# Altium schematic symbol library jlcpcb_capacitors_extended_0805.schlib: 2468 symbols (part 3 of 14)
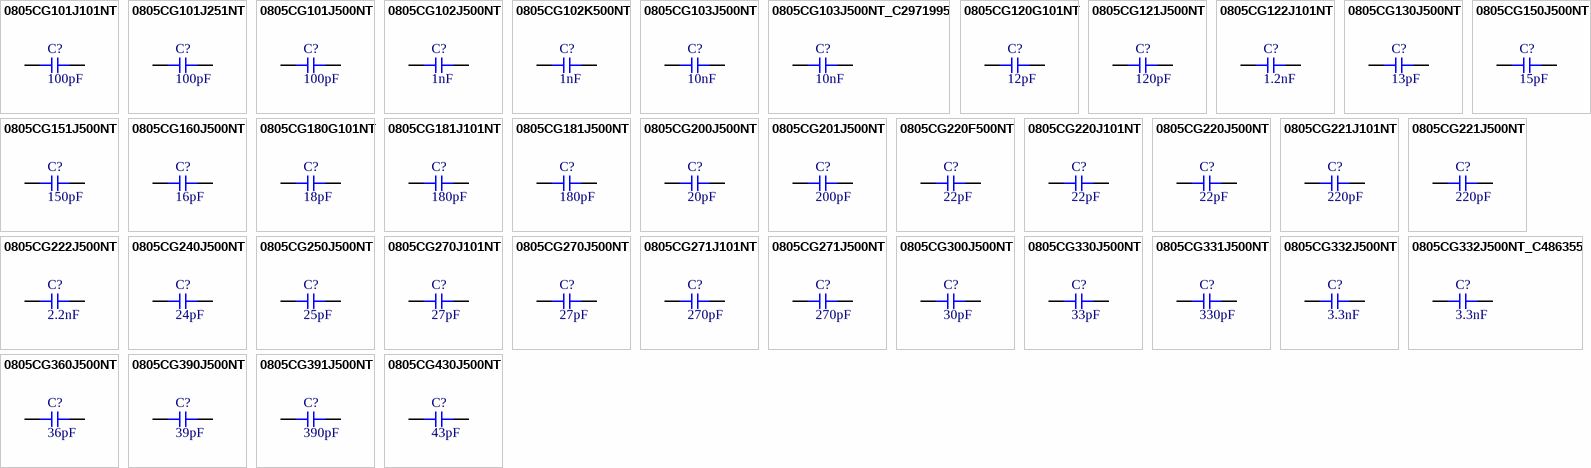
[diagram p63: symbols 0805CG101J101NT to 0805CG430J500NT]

## 0805CG390J500NT
designator C?  Capacitance: 39pF  (hidden comment: *)
Capacitor, Ceramic (MLCC), 39pF, ±5%, 50V, C0G, ±5%, SMD 0805; Manufacturer: FH(Guangdong Fenghua Advanced Tech); Manufacturer Part Number: 0805CG390J500NT
footprint CAP-0805 (0805 (2012M) Capacitor)
pins: 1, 2

## 0805CG391J500NT
designator C?  Capacitance: 390pF  (hidden comment: *)
Capacitor, Ceramic (MLCC), 390pF, ±5%, 50V, C0G, ±5%, SMD 0805; Manufacturer: FH(Guangdong Fenghua Advanced Tech); Manufacturer Part Number: 0805CG391J500NT
footprint CAP-0805 (0805 (2012M) Capacitor)
pins: 1, 2

## 0805CG430J500NT
designator C?  Capacitance: 43pF  (hidden comment: *)
Capacitor, Ceramic (MLCC), 43pF, ±5%, 50V, C0G, ±5%, SMD 0805; Manufacturer: FH(Guangdong Fenghua Advanced Tech); Manufacturer Part Number: 0805CG430J500NT
footprint CAP-0805 (0805 (2012M) Capacitor)
pins: 1, 2

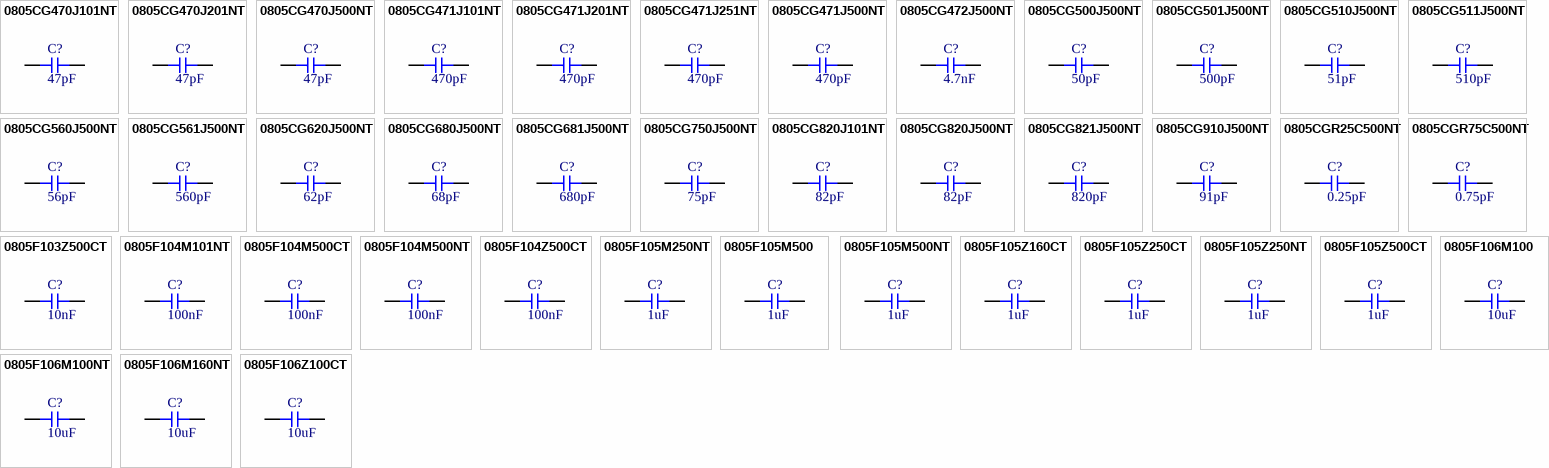
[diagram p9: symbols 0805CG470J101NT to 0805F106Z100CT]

## 0805CG470J101NT
designator C?  Capacitance: 47pF  (hidden comment: *)
Capacitor, Ceramic (MLCC), 47pF, ±5%, 100V, C0G, ±5%, SMD 0805; Manufacturer: FH(Guangdong Fenghua Advanced Tech); Manufacturer Part Number: 0805CG470J101NT
footprint CAP-0805 (0805 (2012M) Capacitor)
pins: 1, 2

## 0805CG470J201NT
designator C?  Capacitance: 47pF  (hidden comment: *)
Capacitor, Ceramic (MLCC), 47pF, ±5%, 200V, C0G, ±5%, SMD 0805; Manufacturer: FH(Guangdong Fenghua Advanced Tech); Manufacturer Part Number: 0805CG470J201NT
footprint CAP-0805 (0805 (2012M) Capacitor)
pins: 1, 2

## 0805CG470J500NT
designator C?  Capacitance: 47pF  (hidden comment: *)
Capacitor, Ceramic (MLCC), 47pF, ±5%, 50V, C0G, ±5%, SMD 0805; Manufacturer: FH(Guangdong Fenghua Advanced Tech); Manufacturer Part Number: 0805CG470J500NT
footprint CAP-0805 (0805 (2012M) Capacitor)
pins: 1, 2

## 0805CG471J101NT
designator C?  Capacitance: 470pF  (hidden comment: *)
Capacitor, Ceramic (MLCC), 470pF, ±5%, 100V, ±5%, SMD 0805; Manufacturer: FH(Guangdong Fenghua Advanced Tech); Manufacturer Part Number: 0805CG471J101NT
footprint CAP-0805 (0805 (2012M) Capacitor)
pins: 1, 2

## 0805CG471J201NT
designator C?  Capacitance: 470pF  (hidden comment: *)
Capacitor, Ceramic (MLCC), 470pF, ±5%, 200V, ±5%, SMD 0805; Manufacturer: FH(Guangdong Fenghua Advanced Tech); Manufacturer Part Number: 0805CG471J201NT
footprint CAP-0805 (0805 (2012M) Capacitor)
pins: 1, 2

## 0805CG471J251NT
designator C?  Capacitance: 470pF  (hidden comment: *)
Capacitor, Ceramic (MLCC), 470pF, ±5%, 250V, C0G, ±5%, SMD 0805; Manufacturer: FH(Guangdong Fenghua Advanced Tech); Manufacturer Part Number: 0805CG471J251NT
footprint CAP-0805 (0805 (2012M) Capacitor)
pins: 1, 2

## 0805CG471J500NT
designator C?  Capacitance: 470pF  (hidden comment: *)
Capacitor, Ceramic (MLCC), 470pF, ±5%, 50V, C0G, ±5%, SMD 0805; Manufacturer: FH(Guangdong Fenghua Advanced Tech); Manufacturer Part Number: 0805CG471J500NT
footprint CAP-0805 (0805 (2012M) Capacitor)
pins: 1, 2

## 0805CG472J500NT
designator C?  Capacitance: 4.7nF  (hidden comment: *)
Capacitor, Ceramic (MLCC), 4.7nF, ±5%, 50V, C0G, ±5%, SMD 0805; Manufacturer: FH(Guangdong Fenghua Advanced Tech); Manufacturer Part Number: 0805CG472J500NT
footprint CAP-0805 (0805 (2012M) Capacitor)
pins: 1, 2

## 0805CG500J500NT
designator C?  Capacitance: 50pF  (hidden comment: *)
Capacitor, Ceramic (MLCC), 50pF, ±5%, 50V, C0G, ±5%, SMD 0805; Manufacturer: FH(Guangdong Fenghua Advanced Tech); Manufacturer Part Number: 0805CG500J500NT
footprint CAP-0805 (0805 (2012M) Capacitor)
pins: 1, 2

## 0805CG501J500NT
designator C?  Capacitance: 500pF  (hidden comment: *)
Capacitor, Ceramic (MLCC), 500pF, ±5%, 50V, C0G, ±5%, SMD 0805; Manufacturer: FH(Guangdong Fenghua Advanced Tech); Manufacturer Part Number: 0805CG501J500NT
footprint CAP-0805 (0805 (2012M) Capacitor)
pins: 1, 2

## 0805CG510J500NT
designator C?  Capacitance: 51pF  (hidden comment: *)
Capacitor, Ceramic (MLCC), 51pF, ±5%, 50V, C0G, ±5%, SMD 0805; Manufacturer: FH(Guangdong Fenghua Advanced Tech); Manufacturer Part Number: 0805CG510J500NT
footprint CAP-0805 (0805 (2012M) Capacitor)
pins: 1, 2

## 0805CG511J500NT
designator C?  Capacitance: 510pF  (hidden comment: *)
Capacitor, Ceramic (MLCC), 510pF, ±5%, 50V, C0G, ±5%, SMD 0805; Manufacturer: FH(Guangdong Fenghua Advanced Tech); Manufacturer Part Number: 0805CG511J500NT
footprint CAP-0805 (0805 (2012M) Capacitor)
pins: 1, 2

## 0805CG560J500NT
designator C?  Capacitance: 56pF  (hidden comment: *)
Capacitor, Ceramic (MLCC), 56pF, ±5%, 50V, C0G, ±5%, SMD 0805; Manufacturer: FH(Guangdong Fenghua Advanced Tech); Manufacturer Part Number: 0805CG560J500NT
footprint CAP-0805 (0805 (2012M) Capacitor)
pins: 1, 2

## 0805CG561J500NT
designator C?  Capacitance: 560pF  (hidden comment: *)
Capacitor, Ceramic (MLCC), 560pF, ±5%, 50V, C0G, ±5%, SMD 0805; Manufacturer: FH(Guangdong Fenghua Advanced Tech); Manufacturer Part Number: 0805CG561J500NT
footprint CAP-0805 (0805 (2012M) Capacitor)
pins: 1, 2

## 0805CG620J500NT
designator C?  Capacitance: 62pF  (hidden comment: *)
Capacitor, Ceramic (MLCC), 62pF, ±5%, 50V, C0G, ±5%, SMD 0805; Manufacturer: FH(Guangdong Fenghua Advanced Tech); Manufacturer Part Number: 0805CG620J500NT
footprint CAP-0805 (0805 (2012M) Capacitor)
pins: 1, 2

## 0805CG680J500NT
designator C?  Capacitance: 68pF  (hidden comment: *)
Capacitor, Ceramic (MLCC), 68pF, ±5%, 50V, C0G, ±5%, SMD 0805; Manufacturer: FH(Guangdong Fenghua Advanced Tech); Manufacturer Part Number: 0805CG680J500NT
footprint CAP-0805 (0805 (2012M) Capacitor)
pins: 1, 2

## 0805CG681J500NT
designator C?  Capacitance: 680pF  (hidden comment: *)
Capacitor, Ceramic (MLCC), 680pF, ±5%, 50V, C0G, ±5%, SMD 0805; Manufacturer: FH(Guangdong Fenghua Advanced Tech); Manufacturer Part Number: 0805CG681J500NT
footprint CAP-0805 (0805 (2012M) Capacitor)
pins: 1, 2

## 0805CG750J500NT
designator C?  Capacitance: 75pF  (hidden comment: *)
Capacitor, Ceramic (MLCC), 75pF, ±5%, 50V, C0G, ±5%, SMD 0805; Manufacturer: FH(Guangdong Fenghua Advanced Tech); Manufacturer Part Number: 0805CG750J500NT
footprint CAP-0805 (0805 (2012M) Capacitor)
pins: 1, 2

## 0805CG820J101NT
designator C?  Capacitance: 82pF  (hidden comment: *)
Capacitor, Ceramic (MLCC), 82pF, ±5%, 100V, ±5%, SMD 0805; Manufacturer: FH(Guangdong Fenghua Advanced Tech); Manufacturer Part Number: 0805CG820J101NT
footprint CAP-0805 (0805 (2012M) Capacitor)
pins: 1, 2

## 0805CG820J500NT
designator C?  Capacitance: 82pF  (hidden comment: *)
Capacitor, Ceramic (MLCC), 82pF, ±5%, 50V, C0G, ±5%, SMD 0805; Manufacturer: FH(Guangdong Fenghua Advanced Tech); Manufacturer Part Number: 0805CG820J500NT
footprint CAP-0805 (0805 (2012M) Capacitor)
pins: 1, 2

## 0805CG821J500NT
designator C?  Capacitance: 820pF  (hidden comment: *)
Capacitor, Ceramic (MLCC), 820pF, ±5%, 50V, C0G, ±5%, SMD 0805; Manufacturer: FH(Guangdong Fenghua Advanced Tech); Manufacturer Part Number: 0805CG821J500NT
footprint CAP-0805 (0805 (2012M) Capacitor)
pins: 1, 2

## 0805CG910J500NT
designator C?  Capacitance: 91pF  (hidden comment: *)
Capacitor, Ceramic (MLCC), 91pF, ±5%, 50V, C0G, ±5%, SMD 0805; Manufacturer: FH(Guangdong Fenghua Advanced Tech); Manufacturer Part Number: 0805CG910J500NT
footprint CAP-0805 (0805 (2012M) Capacitor)
pins: 1, 2

## 0805CGR25C500NT
designator C?  Capacitance: 0.25pF  (hidden comment: *)
Capacitor, Ceramic (MLCC), 0.25pF, ±0.25pF, 50V, C0G, ±0.25pF, SMD 0805; Manufacturer: FH(Guangdong Fenghua Advanced Tech); Manufacturer Part Number: 0805CGR25C500NT
footprint CAP-0805 (0805 (2012M) Capacitor)
pins: 1, 2

## 0805CGR75C500NT
designator C?  Capacitance: 0.75pF  (hidden comment: *)
Capacitor, Ceramic (MLCC), 0.75pF, ±0.25pF, 50V, C0G, ±0.25pF, SMD 0805; Manufacturer: FH(Guangdong Fenghua Advanced Tech); Manufacturer Part Number: 0805CGR75C500NT
footprint CAP-0805 (0805 (2012M) Capacitor)
pins: 1, 2

## 0805F103Z500CT
designator C?  Capacitance: 10nF  (hidden comment: *)
Capacitor, Ceramic (MLCC), 10nF, 50V, Y5V, SMD 0805; Manufacturer: Walsin Tech Corp; Manufacturer Part Number: 0805F103Z500CT; Temperature Rating: -20%~+80%
footprint CAP-0805 (0805 (2012M) Capacitor)
pins: 1, 2

## 0805F104M101NT
designator C?  Capacitance: 100nF  (hidden comment: *)
Capacitor, Ceramic (MLCC), 100nF, ±20%, 100V, Y5V, ±20%, SMD 0805; Manufacturer: FH(Guangdong Fenghua Advanced Tech); Manufacturer Part Number: 0805F104M101NT
footprint CAP-0805 (0805 (2012M) Capacitor)
pins: 1, 2

## 0805F104M500CT
designator C?  Capacitance: 100nF  (hidden comment: *)
Capacitor, Ceramic (MLCC), 100nF, ±20%, 50V, Y5V, ±20%, SMD 0805; Manufacturer: Walsin Tech Corp; Manufacturer Part Number: 0805F104M500CT
footprint CAP-0805 (0805 (2012M) Capacitor)
pins: 1, 2

## 0805F104M500NT
designator C?  Capacitance: 100nF  (hidden comment: *)
Capacitor, Ceramic (MLCC), 100nF, ±20%, 50V, Y5V, ±20%, SMD 0805; Manufacturer: FH(Guangdong Fenghua Advanced Tech); Manufacturer Part Number: 0805F104M500NT
footprint CAP-0805 (0805 (2012M) Capacitor)
pins: 1, 2

## 0805F104Z500CT
designator C?  Capacitance: 100nF  (hidden comment: *)
Capacitor, Ceramic (MLCC), 100nF, 50V, Y5V, SMD 0805; Manufacturer: Walsin Tech Corp; Manufacturer Part Number: 0805F104Z500CT; Temperature Rating: -20%~+80%
footprint CAP-0805 (0805 (2012M) Capacitor)
pins: 1, 2

## 0805F105M250NT
designator C?  Capacitance: 1uF  (hidden comment: *)
Capacitor, Ceramic (MLCC), 1uF, ±20%, 25V, Y5V, ±20%, SMD 0805; Manufacturer: FH(Guangdong Fenghua Advanced Tech); Manufacturer Part Number: 0805F105M250NT
footprint CAP-0805 (0805 (2012M) Capacitor)
pins: 1, 2

## 0805F105M500
designator C?  Capacitance: 1uF  (hidden comment: *)
Capacitor, Ceramic (MLCC), 1uF, ±20%, 50V, Y5V, ±20%, SMD 0805; Manufacturer: Walsin Tech Corp; Manufacturer Part Number: 0805F105M500
footprint CAP-0805 (0805 (2012M) Capacitor)
pins: 1, 2

## 0805F105M500NT
designator C?  Capacitance: 1uF  (hidden comment: *)
Capacitor, Ceramic (MLCC), 1uF, ±20%, 50V, Y5V, ±20%, SMD 0805; Manufacturer: FH(Guangdong Fenghua Advanced Tech); Manufacturer Part Number: 0805F105M500NT
footprint CAP-0805 (0805 (2012M) Capacitor)
pins: 1, 2

## 0805F105Z160CT
designator C?  Capacitance: 1uF  (hidden comment: *)
Capacitor, Ceramic (MLCC), 1uF, 16V, Y5V, SMD 0805; Manufacturer: Walsin Tech Corp; Manufacturer Part Number: 0805F105Z160CT; Temperature Rating: -20%~+80%
footprint CAP-0805 (0805 (2012M) Capacitor)
pins: 1, 2

## 0805F105Z250CT
designator C?  Capacitance: 1uF  (hidden comment: *)
Capacitor, Ceramic (MLCC), 1uF, 25V, Y5V, SMD 0805; Manufacturer: Walsin Tech Corp; Manufacturer Part Number: 0805F105Z250CT; Temperature Rating: -20%~+80%
footprint CAP-0805 (0805 (2012M) Capacitor)
pins: 1, 2

## 0805F105Z250NT
designator C?  Capacitance: 1uF  (hidden comment: *)
Capacitor, Ceramic (MLCC), 1uF, 25V, Y5V, SMD 0805; Manufacturer: FH(Guangdong Fenghua Advanced Tech); Manufacturer Part Number: 0805F105Z250NT; Temperature Rating: -20%~+80%
footprint CAP-0805 (0805 (2012M) Capacitor)
pins: 1, 2

## 0805F105Z500CT
designator C?  Capacitance: 1uF  (hidden comment: *)
Capacitor, Ceramic (MLCC), 1uF, 50V, Y5V, SMD 0805; Manufacturer: Walsin Tech Corp; Manufacturer Part Number: 0805F105Z500CT; Temperature Rating: -20%~+80%
footprint CAP-0805 (0805 (2012M) Capacitor)
pins: 1, 2

## 0805F106M100
designator C?  Capacitance: 10uF  (hidden comment: *)
Capacitor, Ceramic (MLCC), 10uF, ±20%, 10V, Y5V, ±20%, SMD 0805; Manufacturer: Walsin Tech Corp; Manufacturer Part Number: 0805F106M100
footprint CAP-0805 (0805 (2012M) Capacitor)
pins: 1, 2

## 0805F106M100NT
designator C?  Capacitance: 10uF  (hidden comment: *)
Capacitor, Ceramic (MLCC), 10uF, ±20%, 10V, Y5V, ±20%, SMD 0805; Manufacturer: FH(Guangdong Fenghua Advanced Tech); Manufacturer Part Number: 0805F106M100NT
footprint CAP-0805 (0805 (2012M) Capacitor)
pins: 1, 2

## 0805F106M160NT
designator C?  Capacitance: 10uF  (hidden comment: *)
Capacitor, Ceramic (MLCC), 10uF, ±20%, 16V, Y5V, ±20%, SMD 0805; Manufacturer: FH(Guangdong Fenghua Advanced Tech); Manufacturer Part Number: 0805F106M160NT
footprint CAP-0805 (0805 (2012M) Capacitor)
pins: 1, 2

## 0805F106Z100CT
designator C?  Capacitance: 10uF  (hidden comment: *)
Capacitor, Ceramic (MLCC), 10uF, 10V, Y5V, SMD 0805; Manufacturer: Walsin Tech Corp; Manufacturer Part Number: 0805F106Z100CT; Temperature Rating: -20%~+80%
footprint CAP-0805 (0805 (2012M) Capacitor)
pins: 1, 2

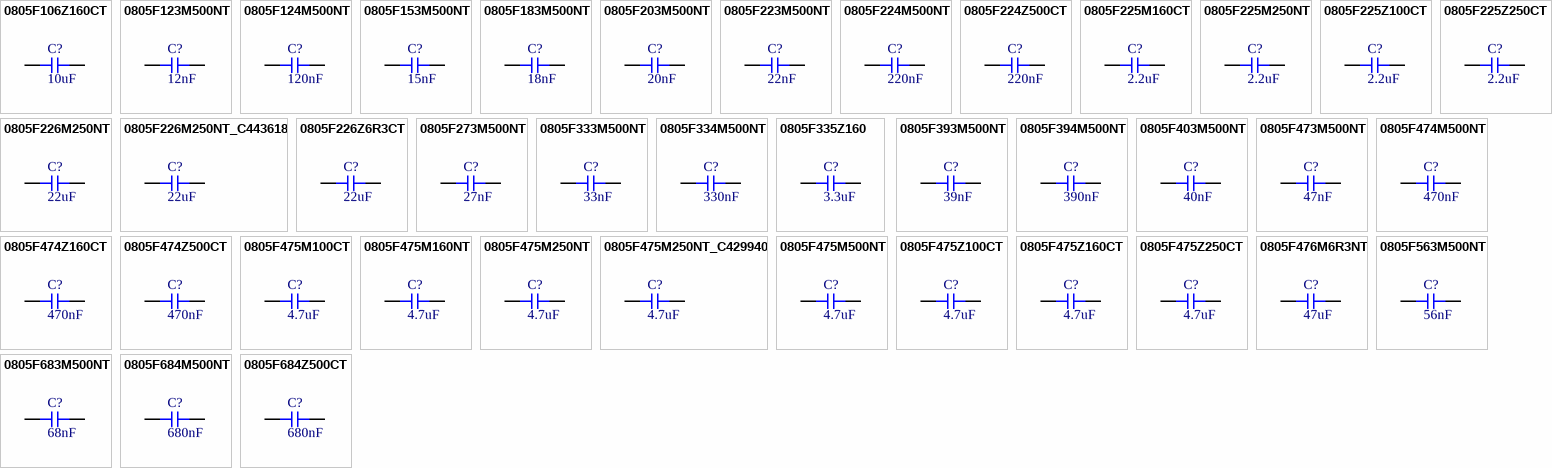
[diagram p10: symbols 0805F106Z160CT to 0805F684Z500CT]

## 0805F106Z160CT
designator C?  Capacitance: 10uF  (hidden comment: *)
Capacitor, Ceramic (MLCC), 10uF, 16V, Y5V, SMD 0805; Manufacturer: Walsin Tech Corp; Manufacturer Part Number: 0805F106Z160CT; Temperature Rating: -20%~+80%
footprint CAP-0805 (0805 (2012M) Capacitor)
pins: 1, 2

## 0805F123M500NT
designator C?  Capacitance: 12nF  (hidden comment: *)
Capacitor, Ceramic (MLCC), 12nF, ±20%, 50V, Y5V, ±20%, SMD 0805; Manufacturer: FH(Guangdong Fenghua Advanced Tech); Manufacturer Part Number: 0805F123M500NT
footprint CAP-0805 (0805 (2012M) Capacitor)
pins: 1, 2

## 0805F124M500NT
designator C?  Capacitance: 120nF  (hidden comment: *)
Capacitor, Ceramic (MLCC), 120nF, ±20%, 50V, Y5V, ±20%, SMD 0805; Manufacturer: FH(Guangdong Fenghua Advanced Tech); Manufacturer Part Number: 0805F124M500NT
footprint CAP-0805 (0805 (2012M) Capacitor)
pins: 1, 2

## 0805F153M500NT
designator C?  Capacitance: 15nF  (hidden comment: *)
Capacitor, Ceramic (MLCC), 15nF, ±20%, 50V, Y5V, ±20%, SMD 0805; Manufacturer: FH(Guangdong Fenghua Advanced Tech); Manufacturer Part Number: 0805F153M500NT
footprint CAP-0805 (0805 (2012M) Capacitor)
pins: 1, 2

## 0805F183M500NT
designator C?  Capacitance: 18nF  (hidden comment: *)
Capacitor, Ceramic (MLCC), 18nF, ±20%, 50V, Y5V, ±20%, SMD 0805; Manufacturer: FH(Guangdong Fenghua Advanced Tech); Manufacturer Part Number: 0805F183M500NT
footprint CAP-0805 (0805 (2012M) Capacitor)
pins: 1, 2

## 0805F203M500NT
designator C?  Capacitance: 20nF  (hidden comment: *)
Capacitor, Ceramic (MLCC), 20nF, ±20%, 50V, Y5V, ±20%, SMD 0805; Manufacturer: FH(Guangdong Fenghua Advanced Tech); Manufacturer Part Number: 0805F203M500NT
footprint CAP-0805 (0805 (2012M) Capacitor)
pins: 1, 2

## 0805F223M500NT
designator C?  Capacitance: 22nF  (hidden comment: *)
Capacitor, Ceramic (MLCC), 22nF, ±20%, 50V, Y5V, ±20%, SMD 0805; Manufacturer: FH(Guangdong Fenghua Advanced Tech); Manufacturer Part Number: 0805F223M500NT
footprint CAP-0805 (0805 (2012M) Capacitor)
pins: 1, 2

## 0805F224M500NT
designator C?  Capacitance: 220nF  (hidden comment: *)
Capacitor, Ceramic (MLCC), 220nF, ±20%, 50V, Y5V, ±20%, SMD 0805; Manufacturer: FH(Guangdong Fenghua Advanced Tech); Manufacturer Part Number: 0805F224M500NT
footprint CAP-0805 (0805 (2012M) Capacitor)
pins: 1, 2

## 0805F224Z500CT
designator C?  Capacitance: 220nF  (hidden comment: *)
Capacitor, Ceramic (MLCC), 220nF, 50V, Y5V, SMD 0805; Manufacturer: Walsin Tech Corp; Manufacturer Part Number: 0805F224Z500CT; Temperature Rating: -20%~+80%
footprint CAP-0805 (0805 (2012M) Capacitor)
pins: 1, 2

## 0805F225M160CT
designator C?  Capacitance: 2.2uF  (hidden comment: *)
Capacitor, Ceramic (MLCC), 2.2uF, ±20%, 16V, Y5V, ±20%, SMD 0805; Manufacturer: Walsin Tech Corp; Manufacturer Part Number: 0805F225M160CT
footprint CAP-0805 (0805 (2012M) Capacitor)
pins: 1, 2

## 0805F225M250NT
designator C?  Capacitance: 2.2uF  (hidden comment: *)
Capacitor, Ceramic (MLCC), 2.2uF, ±20%, 25V, Y5V, ±20%, SMD 0805; Manufacturer: FH(Guangdong Fenghua Advanced Tech); Manufacturer Part Number: 0805F225M250NT
footprint CAP-0805 (0805 (2012M) Capacitor)
pins: 1, 2

## 0805F225Z100CT
designator C?  Capacitance: 2.2uF  (hidden comment: *)
Capacitor, Ceramic (MLCC), 2.2uF, 10V, Y5V, SMD 0805; Manufacturer: Walsin Tech Corp; Manufacturer Part Number: 0805F225Z100CT; Temperature Rating: -20%~+80%
footprint CAP-0805 (0805 (2012M) Capacitor)
pins: 1, 2

## 0805F225Z250CT
designator C?  Capacitance: 2.2uF  (hidden comment: *)
Capacitor, Ceramic (MLCC), 2.2uF, 25V, Y5V, SMD 0805; Manufacturer: Walsin Tech Corp; Manufacturer Part Number: 0805F225Z250CT; Temperature Rating: -20%~+80%
footprint CAP-0805 (0805 (2012M) Capacitor)
pins: 1, 2

## 0805F226M250NT
designator C?  Capacitance: 22uF  (hidden comment: *)
Capacitor, Ceramic (MLCC), 22uF, ±20%, 25V, Y5V, ±20%, SMD 0805; Manufacturer: FH(Guangdong Fenghua Advanced Tech); Manufacturer Part Number: 0805F226M250NT
footprint CAP-0805 (0805 (2012M) Capacitor)
pins: 1, 2

## 0805F226M250NT_C443618
designator C?  Capacitance: 22uF  (hidden comment: *)
Capacitor, Ceramic (MLCC), 22uF, ±20%, 25V, Y5V, ±20%, SMD 0805; Manufacturer: FH(Guangdong Fenghua Advanced Tech); Manufacturer Part Number: 0805F226M250NT
footprint CAP-0805 (0805 (2012M) Capacitor)
pins: 1, 2

## 0805F226Z6R3CT
designator C?  Capacitance: 22uF  (hidden comment: *)
Capacitor, Ceramic (MLCC), 22uF, 6.3V, Y5V, SMD 0805; Manufacturer: Walsin Tech Corp; Manufacturer Part Number: 0805F226Z6R3CT; Temperature Rating: -20%~+80%
footprint CAP-0805 (0805 (2012M) Capacitor)
pins: 1, 2

## 0805F273M500NT
designator C?  Capacitance: 27nF  (hidden comment: *)
Capacitor, Ceramic (MLCC), 27nF, ±20%, 50V, Y5V, ±20%, SMD 0805; Manufacturer: FH(Guangdong Fenghua Advanced Tech); Manufacturer Part Number: 0805F273M500NT
footprint CAP-0805 (0805 (2012M) Capacitor)
pins: 1, 2

## 0805F333M500NT
designator C?  Capacitance: 33nF  (hidden comment: *)
Capacitor, Ceramic (MLCC), 33nF, ±20%, 50V, Y5V, ±20%, SMD 0805; Manufacturer: FH(Guangdong Fenghua Advanced Tech); Manufacturer Part Number: 0805F333M500NT
footprint CAP-0805 (0805 (2012M) Capacitor)
pins: 1, 2

## 0805F334M500NT
designator C?  Capacitance: 330nF  (hidden comment: *)
Capacitor, Ceramic (MLCC), 330nF, ±20%, 50V, Y5V, ±20%, SMD 0805; Manufacturer: FH(Guangdong Fenghua Advanced Tech); Manufacturer Part Number: 0805F334M500NT
footprint CAP-0805 (0805 (2012M) Capacitor)
pins: 1, 2

## 0805F335Z160
designator C?  Capacitance: 3.3uF  (hidden comment: *)
Capacitor, Ceramic (MLCC), 3.3uF, 16V, Y5V, SMD 0805; Manufacturer: Walsin Tech Corp; Manufacturer Part Number: 0805F335Z160; Temperature Rating: -20%~+80%
footprint CAP-0805 (0805 (2012M) Capacitor)
pins: 1, 2

## 0805F393M500NT
designator C?  Capacitance: 39nF  (hidden comment: *)
Capacitor, Ceramic (MLCC), 39nF, ±20%, 50V, Y5V, ±20%, SMD 0805; Manufacturer: FH(Guangdong Fenghua Advanced Tech); Manufacturer Part Number: 0805F393M500NT
footprint CAP-0805 (0805 (2012M) Capacitor)
pins: 1, 2

## 0805F394M500NT
designator C?  Capacitance: 390nF  (hidden comment: *)
Capacitor, Ceramic (MLCC), 390nF, ±20%, 50V, Y5V, ±20%, SMD 0805; Manufacturer: FH(Guangdong Fenghua Advanced Tech); Manufacturer Part Number: 0805F394M500NT
footprint CAP-0805 (0805 (2012M) Capacitor)
pins: 1, 2

## 0805F403M500NT
designator C?  Capacitance: 40nF  (hidden comment: *)
Capacitor, Ceramic (MLCC), 40nF, ±20%, 50V, Y5V, ±20%, SMD 0805; Manufacturer: FH(Guangdong Fenghua Advanced Tech); Manufacturer Part Number: 0805F403M500NT
footprint CAP-0805 (0805 (2012M) Capacitor)
pins: 1, 2

## 0805F473M500NT
designator C?  Capacitance: 47nF  (hidden comment: *)
Capacitor, Ceramic (MLCC), 47nF, ±20%, 50V, Y5V, ±20%, SMD 0805; Manufacturer: FH(Guangdong Fenghua Advanced Tech); Manufacturer Part Number: 0805F473M500NT
footprint CAP-0805 (0805 (2012M) Capacitor)
pins: 1, 2

## 0805F474M500NT
designator C?  Capacitance: 470nF  (hidden comment: *)
Capacitor, Ceramic (MLCC), 470nF, ±20%, 50V, Y5V, ±20%, SMD 0805; Manufacturer: FH(Guangdong Fenghua Advanced Tech); Manufacturer Part Number: 0805F474M500NT
footprint CAP-0805 (0805 (2012M) Capacitor)
pins: 1, 2

## 0805F474Z160CT
designator C?  Capacitance: 470nF  (hidden comment: *)
Capacitor, Ceramic (MLCC), 470nF, 16V, Y5V, SMD 0805; Manufacturer: Walsin Tech Corp; Manufacturer Part Number: 0805F474Z160CT; Temperature Rating: -20%~+80%
footprint CAP-0805 (0805 (2012M) Capacitor)
pins: 1, 2

## 0805F474Z500CT
designator C?  Capacitance: 470nF  (hidden comment: *)
Capacitor, Ceramic (MLCC), 470nF, 50V, Y5V, SMD 0805; Manufacturer: Walsin Tech Corp; Manufacturer Part Number: 0805F474Z500CT; Temperature Rating: -20%~+80%
footprint CAP-0805 (0805 (2012M) Capacitor)
pins: 1, 2

## 0805F475M100CT
designator C?  Capacitance: 4.7uF  (hidden comment: *)
Capacitor, Ceramic (MLCC), 4.7uF, ±20%, 10V, Y5V, ±20%, SMD 0805; Manufacturer: Walsin Tech Corp; Manufacturer Part Number: 0805F475M100CT
footprint CAP-0805 (0805 (2012M) Capacitor)
pins: 1, 2

## 0805F475M160NT
designator C?  Capacitance: 4.7uF  (hidden comment: *)
Capacitor, Ceramic (MLCC), 4.7uF, ±20%, 16V, Y5V, ±20%, SMD 0805; Manufacturer: FH(Guangdong Fenghua Advanced Tech); Manufacturer Part Number: 0805F475M160NT
footprint CAP-0805 (0805 (2012M) Capacitor)
pins: 1, 2

## 0805F475M250NT
designator C?  Capacitance: 4.7uF  (hidden comment: *)
Capacitor, Ceramic (MLCC), 4.7uF, ±20%, 25V, Y5V, ±20%, SMD 0805; Manufacturer: FH(Guangdong Fenghua Advanced Tech); Manufacturer Part Number: 0805F475M250NT
footprint CAP-0805 (0805 (2012M) Capacitor)
pins: 1, 2

## 0805F475M250NT_C429940
designator C?  Capacitance: 4.7uF  (hidden comment: *)
Capacitor, Ceramic (MLCC), 4.7uF, ±20%, 25V, Y5V, ±20%, SMD 0805; Manufacturer: FH(Guangdong Fenghua Advanced Tech); Manufacturer Part Number: 0805F475M250NT
footprint CAP-0805 (0805 (2012M) Capacitor)
pins: 1, 2

## 0805F475M500NT
designator C?  Capacitance: 4.7uF  (hidden comment: *)
Capacitor, Ceramic (MLCC), 4.7uF, ±20%, 50V, Y5V, ±20%, SMD 0805; Manufacturer: FH(Guangdong Fenghua Advanced Tech); Manufacturer Part Number: 0805F475M500NT
footprint CAP-0805 (0805 (2012M) Capacitor)
pins: 1, 2

## 0805F475Z100CT
designator C?  Capacitance: 4.7uF  (hidden comment: *)
Capacitor, Ceramic (MLCC), 4.7uF, 10V, Y5V, SMD 0805; Manufacturer: Walsin Tech Corp; Manufacturer Part Number: 0805F475Z100CT; Temperature Rating: -20%~+80%
footprint CAP-0805 (0805 (2012M) Capacitor)
pins: 1, 2

## 0805F475Z160CT
designator C?  Capacitance: 4.7uF  (hidden comment: *)
Capacitor, Ceramic (MLCC), 4.7uF, 16V, Y5V, SMD 0805; Manufacturer: Walsin Tech Corp; Manufacturer Part Number: 0805F475Z160CT; Temperature Rating: -20%~+80%
footprint CAP-0805 (0805 (2012M) Capacitor)
pins: 1, 2

## 0805F475Z250CT
designator C?  Capacitance: 4.7uF  (hidden comment: *)
Capacitor, Ceramic (MLCC), 4.7uF, 25V, Y5V, SMD 0805; Manufacturer: Walsin Tech Corp; Manufacturer Part Number: 0805F475Z250CT; Temperature Rating: -20%~+80%
footprint CAP-0805 (0805 (2012M) Capacitor)
pins: 1, 2

## 0805F476M6R3NT
designator C?  Capacitance: 47uF  (hidden comment: *)
Capacitor, Ceramic (MLCC), 47uF, ±20%, 6.3V, Y5V, ±20%, SMD 0805; Manufacturer: FH(Guangdong Fenghua Advanced Tech); Manufacturer Part Number: 0805F476M6R3NT
footprint CAP-0805 (0805 (2012M) Capacitor)
pins: 1, 2

## 0805F563M500NT
designator C?  Capacitance: 56nF  (hidden comment: *)
Capacitor, Ceramic (MLCC), 56nF, ±20%, 50V, Y5V, ±20%, SMD 0805; Manufacturer: FH(Guangdong Fenghua Advanced Tech); Manufacturer Part Number: 0805F563M500NT
footprint CAP-0805 (0805 (2012M) Capacitor)
pins: 1, 2

## 0805F683M500NT
designator C?  Capacitance: 68nF  (hidden comment: *)
Capacitor, Ceramic (MLCC), 68nF, ±20%, 50V, Y5V, ±20%, SMD 0805; Manufacturer: FH(Guangdong Fenghua Advanced Tech); Manufacturer Part Number: 0805F683M500NT
footprint CAP-0805 (0805 (2012M) Capacitor)
pins: 1, 2

## 0805F684M500NT
designator C?  Capacitance: 680nF  (hidden comment: *)
Capacitor, Ceramic (MLCC), 680nF, ±20%, 50V, Y5V, ±20%, SMD 0805; Manufacturer: FH(Guangdong Fenghua Advanced Tech); Manufacturer Part Number: 0805F684M500NT
footprint CAP-0805 (0805 (2012M) Capacitor)
pins: 1, 2

## 0805F684Z500CT
designator C?  Capacitance: 680nF  (hidden comment: *)
Capacitor, Ceramic (MLCC), 680nF, 50V, Y5V, SMD 0805; Manufacturer: Walsin Tech Corp; Manufacturer Part Number: 0805F684Z500CT; Temperature Rating: -20%~+80%
footprint CAP-0805 (0805 (2012M) Capacitor)
pins: 1, 2

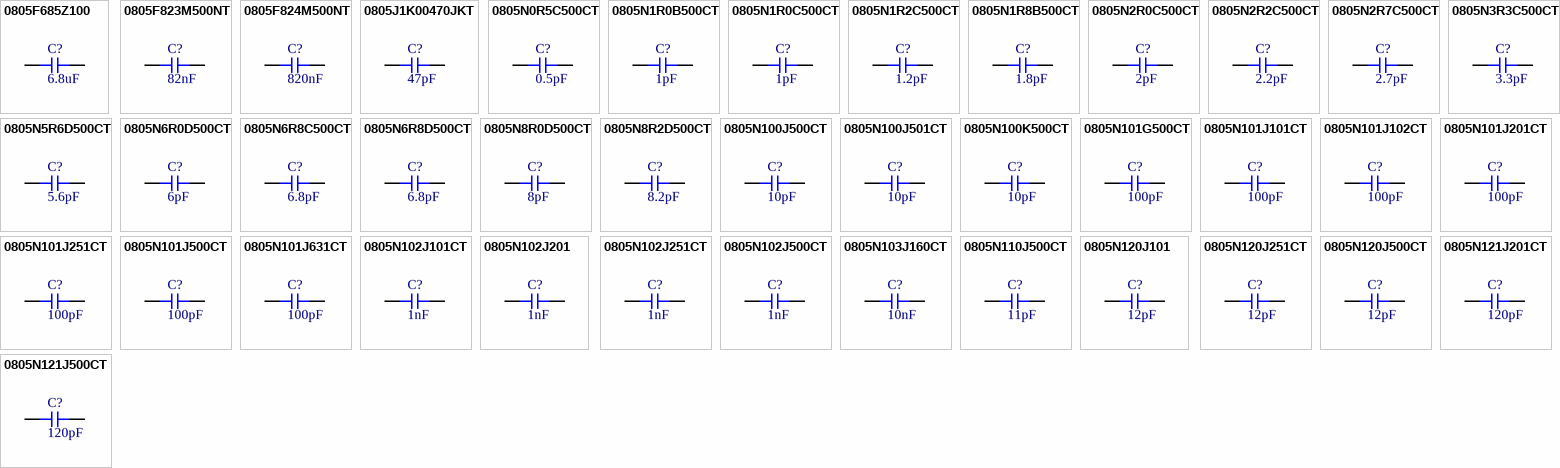
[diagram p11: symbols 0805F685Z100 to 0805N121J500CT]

## 0805F685Z100
designator C?  Capacitance: 6.8uF  (hidden comment: *)
Capacitor, Ceramic (MLCC), 6.8uF, 10V, Y5V, SMD 0805; Manufacturer: Walsin Tech Corp; Manufacturer Part Number: 0805F685Z100; Temperature Rating: -20%~+80%
footprint CAP-0805 (0805 (2012M) Capacitor)
pins: 1, 2

## 0805F823M500NT
designator C?  Capacitance: 82nF  (hidden comment: *)
Capacitor, Ceramic (MLCC), 82nF, ±20%, 50V, Y5V, ±20%, SMD 0805; Manufacturer: FH(Guangdong Fenghua Advanced Tech); Manufacturer Part Number: 0805F823M500NT
footprint CAP-0805 (0805 (2012M) Capacitor)
pins: 1, 2

## 0805F824M500NT
designator C?  Capacitance: 820nF  (hidden comment: *)
Capacitor, Ceramic (MLCC), 820nF, ±20%, 50V, Y5V, ±20%, SMD 0805; Manufacturer: FH(Guangdong Fenghua Advanced Tech); Manufacturer Part Number: 0805F824M500NT
footprint CAP-0805 (0805 (2012M) Capacitor)
pins: 1, 2

## 0805J1K00470JKT
designator C?  Capacitance: 47pF  (hidden comment: *)
Capacitor, Ceramic (MLCC), 47pF, ±5%, 1kV, C0G, ±5%, SMD 0805; Manufacturer: Knowles; Manufacturer Part Number: 0805J1K00470JKT
footprint CAP-0805 (0805 (2012M) Capacitor)
pins: 1, 2

## 0805N0R5C500CT
designator C?  Capacitance: 0.5pF  (hidden comment: *)
Capacitor, Ceramic (MLCC), 0.5pF, ±0.25pF, 50V, NP0, ±0.25pF, SMD 0805; Manufacturer: Walsin Tech Corp; Manufacturer Part Number: 0805N0R5C500CT
footprint CAP-0805 (0805 (2012M) Capacitor)
pins: 1, 2

## 0805N1R0B500CT
designator C?  Capacitance: 1pF  (hidden comment: *)
Capacitor, Ceramic (MLCC), 1pF, ±0.1pF, 50V, NP0, ±0.1pF, SMD 0805; Manufacturer: Walsin Tech Corp; Manufacturer Part Number: 0805N1R0B500CT
footprint CAP-0805 (0805 (2012M) Capacitor)
pins: 1, 2

## 0805N1R0C500CT
designator C?  Capacitance: 1pF  (hidden comment: *)
Capacitor, Ceramic (MLCC), 1pF, ±0.25pF, 50V, NP0, ±0.25pF, SMD 0805; Manufacturer: Walsin Tech Corp; Manufacturer Part Number: 0805N1R0C500CT
footprint CAP-0805 (0805 (2012M) Capacitor)
pins: 1, 2

## 0805N1R2C500CT
designator C?  Capacitance: 1.2pF  (hidden comment: *)
Capacitor, Ceramic (MLCC), 1.2pF, ±0.25pF, 50V, NP0, ±0.25pF, SMD 0805; Manufacturer: Walsin Tech Corp; Manufacturer Part Number: 0805N1R2C500CT
footprint CAP-0805 (0805 (2012M) Capacitor)
pins: 1, 2

## 0805N1R8B500CT
designator C?  Capacitance: 1.8pF  (hidden comment: *)
Capacitor, Ceramic (MLCC), 1.8pF, ±0.1pF, 50V, NP0, ±0.1pF, SMD 0805; Manufacturer: Walsin Tech Corp; Manufacturer Part Number: 0805N1R8B500CT
footprint CAP-0805 (0805 (2012M) Capacitor)
pins: 1, 2

## 0805N2R0C500CT
designator C?  Capacitance: 2pF  (hidden comment: *)
Capacitor, Ceramic (MLCC), 2pF, ±0.25pF, 50V, NP0, ±0.25pF, SMD 0805; Manufacturer: Walsin Tech Corp; Manufacturer Part Number: 0805N2R0C500CT
footprint CAP-0805 (0805 (2012M) Capacitor)
pins: 1, 2

## 0805N2R2C500CT
designator C?  Capacitance: 2.2pF  (hidden comment: *)
Capacitor, Ceramic (MLCC), 2.2pF, ±0.25pF, 50V, NP0, ±0.25pF, SMD 0805; Manufacturer: Walsin Tech Corp; Manufacturer Part Number: 0805N2R2C500CT
footprint CAP-0805 (0805 (2012M) Capacitor)
pins: 1, 2

## 0805N2R7C500CT
designator C?  Capacitance: 2.7pF  (hidden comment: *)
Capacitor, Ceramic (MLCC), 2.7pF, ±0.25pF, 50V, NP0, ±0.25pF, SMD 0805; Manufacturer: Walsin Tech Corp; Manufacturer Part Number: 0805N2R7C500CT
footprint CAP-0805 (0805 (2012M) Capacitor)
pins: 1, 2

## 0805N3R3C500CT
designator C?  Capacitance: 3.3pF  (hidden comment: *)
Capacitor, Ceramic (MLCC), 3.3pF, ±0.25pF, 50V, NP0, ±0.25pF, SMD 0805; Manufacturer: Walsin Tech Corp; Manufacturer Part Number: 0805N3R3C500CT
footprint CAP-0805 (0805 (2012M) Capacitor)
pins: 1, 2

## 0805N5R6D500CT
designator C?  Capacitance: 5.6pF  (hidden comment: *)
Capacitor, Ceramic (MLCC), 5.6pF, ±0.5pF, 50V, NP0, ±0.5pF, SMD 0805; Manufacturer: Walsin Tech Corp; Manufacturer Part Number: 0805N5R6D500CT
footprint CAP-0805 (0805 (2012M) Capacitor)
pins: 1, 2

## 0805N6R0D500CT
designator C?  Capacitance: 6pF  (hidden comment: *)
Capacitor, Ceramic (MLCC), 6pF, ±0.5pF, 50V, NP0, ±0.5pF, SMD 0805; Manufacturer: Walsin Tech Corp; Manufacturer Part Number: 0805N6R0D500CT
footprint CAP-0805 (0805 (2012M) Capacitor)
pins: 1, 2

## 0805N6R8C500CT
designator C?  Capacitance: 6.8pF  (hidden comment: *)
Capacitor, Ceramic (MLCC), 6.8pF, ±0.25pF, 50V, NP0, ±0.25pF, SMD 0805; Manufacturer: Walsin Tech Corp; Manufacturer Part Number: 0805N6R8C500CT
footprint CAP-0805 (0805 (2012M) Capacitor)
pins: 1, 2

## 0805N6R8D500CT
designator C?  Capacitance: 6.8pF  (hidden comment: *)
Capacitor, Ceramic (MLCC), 6.8pF, ±0.5pF, 50V, NP0, ±0.5pF, SMD 0805; Manufacturer: Walsin Tech Corp; Manufacturer Part Number: 0805N6R8D500CT
footprint CAP-0805 (0805 (2012M) Capacitor)
pins: 1, 2

## 0805N8R0D500CT
designator C?  Capacitance: 8pF  (hidden comment: *)
Capacitor, Ceramic (MLCC), 8pF, ±0.5pF, 50V, NP0, ±0.5pF, SMD 0805; Manufacturer: Walsin Tech Corp; Manufacturer Part Number: 0805N8R0D500CT
footprint CAP-0805 (0805 (2012M) Capacitor)
pins: 1, 2

## 0805N8R2D500CT
designator C?  Capacitance: 8.2pF  (hidden comment: *)
Capacitor, Ceramic (MLCC), 8.2pF, ±0.5pF, 50V, NP0, ±0.5pF, SMD 0805; Manufacturer: Walsin Tech Corp; Manufacturer Part Number: 0805N8R2D500CT
footprint CAP-0805 (0805 (2012M) Capacitor)
pins: 1, 2

## 0805N100J500CT
designator C?  Capacitance: 10pF  (hidden comment: *)
Capacitor, Ceramic (MLCC), 10pF, ±5%, 50V, NP0, ±5%, SMD 0805; Manufacturer: Walsin Tech Corp; Manufacturer Part Number: 0805N100J500CT
footprint CAP-0805 (0805 (2012M) Capacitor)
pins: 1, 2

## 0805N100J501CT
designator C?  Capacitance: 10pF  (hidden comment: *)
Capacitor, Ceramic (MLCC), 10pF, ±5%, 500V, NP0, ±5%, SMD 0805; Manufacturer: Walsin Tech Corp; Manufacturer Part Number: 0805N100J501CT
footprint CAP-0805 (0805 (2012M) Capacitor)
pins: 1, 2

## 0805N100K500CT
designator C?  Capacitance: 10pF  (hidden comment: *)
Capacitor, Ceramic (MLCC), 10pF, ±10%, 50V, NP0, ±10%, SMD 0805; Manufacturer: Walsin Tech Corp; Manufacturer Part Number: 0805N100K500CT
footprint CAP-0805 (0805 (2012M) Capacitor)
pins: 1, 2

## 0805N101G500CT
designator C?  Capacitance: 100pF  (hidden comment: *)
Capacitor, Ceramic (MLCC), 100pF, ±2%, 50V, NP0, ±2%, SMD 0805; Manufacturer: Walsin Tech Corp; Manufacturer Part Number: 0805N101G500CT
footprint CAP-0805 (0805 (2012M) Capacitor)
pins: 1, 2

## 0805N101J101CT
designator C?  Capacitance: 100pF  (hidden comment: *)
Capacitor, Ceramic (MLCC), 100pF, ±5%, 100V, NP0, ±5%, SMD 0805; Manufacturer: Walsin Tech Corp; Manufacturer Part Number: 0805N101J101CT
footprint CAP-0805 (0805 (2012M) Capacitor)
pins: 1, 2

## 0805N101J102CT
designator C?  Capacitance: 100pF  (hidden comment: *)
Capacitor, Ceramic (MLCC), 100pF, ±5%, 1kV, NP0, ±5%, SMD 0805; Manufacturer: Walsin Tech Corp; Manufacturer Part Number: 0805N101J102CT
footprint CAP-0805 (0805 (2012M) Capacitor)
pins: 1, 2

## 0805N101J201CT
designator C?  Capacitance: 100pF  (hidden comment: *)
Capacitor, Ceramic (MLCC), 100pF, ±5%, 200V, NP0, ±5%, SMD 0805; Manufacturer: Walsin Tech Corp; Manufacturer Part Number: 0805N101J201CT
footprint CAP-0805 (0805 (2012M) Capacitor)
pins: 1, 2

## 0805N101J251CT
designator C?  Capacitance: 100pF  (hidden comment: *)
Capacitor, Ceramic (MLCC), 100pF, ±5%, 250V, NP0, ±5%, SMD 0805; Manufacturer: Walsin Tech Corp; Manufacturer Part Number: 0805N101J251CT
footprint CAP-0805 (0805 (2012M) Capacitor)
pins: 1, 2

## 0805N101J500CT
designator C?  Capacitance: 100pF  (hidden comment: *)
Capacitor, Ceramic (MLCC), 100pF, ±5%, 50V, NP0, ±5%, SMD 0805; Manufacturer: Walsin Tech Corp; Manufacturer Part Number: 0805N101J500CT
footprint CAP-0805 (0805 (2012M) Capacitor)
pins: 1, 2

## 0805N101J631CT
designator C?  Capacitance: 100pF  (hidden comment: *)
Capacitor, Ceramic (MLCC), 100pF, ±5%, 630V, NP0, ±5%, SMD 0805; Manufacturer: Walsin Tech Corp; Manufacturer Part Number: 0805N101J631CT
footprint CAP-0805 (0805 (2012M) Capacitor)
pins: 1, 2

## 0805N102J101CT
designator C?  Capacitance: 1nF  (hidden comment: *)
Capacitor, Ceramic (MLCC), 1nF, ±5%, 100V, NP0, ±5%, SMD 0805; Manufacturer: Walsin Tech Corp; Manufacturer Part Number: 0805N102J101CT
footprint CAP-0805 (0805 (2012M) Capacitor)
pins: 1, 2

## 0805N102J201
designator C?  Capacitance: 1nF  (hidden comment: *)
Capacitor, Ceramic (MLCC), 1nF, ±5%, 200V, NP0, ±5%, SMD 0805; Manufacturer: Walsin Tech Corp; Manufacturer Part Number: 0805N102J201
footprint CAP-0805 (0805 (2012M) Capacitor)
pins: 1, 2

## 0805N102J251CT
designator C?  Capacitance: 1nF  (hidden comment: *)
Capacitor, Ceramic (MLCC), 1nF, ±5%, 250V, NP0, ±5%, SMD 0805; Manufacturer: Walsin Tech Corp; Manufacturer Part Number: 0805N102J251CT
footprint CAP-0805 (0805 (2012M) Capacitor)
pins: 1, 2

## 0805N102J500CT
designator C?  Capacitance: 1nF  (hidden comment: *)
Capacitor, Ceramic (MLCC), 1nF, ±5%, 50V, NP0, ±5%, SMD 0805; Manufacturer: Walsin Tech Corp; Manufacturer Part Number: 0805N102J500CT
footprint CAP-0805 (0805 (2012M) Capacitor)
pins: 1, 2

## 0805N103J160CT
designator C?  Capacitance: 10nF  (hidden comment: *)
Capacitor, Ceramic (MLCC), 10nF, ±5%, 16V, NP0, ±5%, SMD 0805; Manufacturer: Walsin Tech Corp; Manufacturer Part Number: 0805N103J160CT
footprint CAP-0805 (0805 (2012M) Capacitor)
pins: 1, 2

## 0805N110J500CT
designator C?  Capacitance: 11pF  (hidden comment: *)
Capacitor, Ceramic (MLCC), 11pF, ±5%, 50V, NP0, ±5%, SMD 0805; Manufacturer: Walsin Tech Corp; Manufacturer Part Number: 0805N110J500CT
footprint CAP-0805 (0805 (2012M) Capacitor)
pins: 1, 2

## 0805N120J101
designator C?  Capacitance: 12pF  (hidden comment: *)
Capacitor, Ceramic (MLCC), 12pF, ±5%, 100V, NP0, ±5%, SMD 0805; Manufacturer: Walsin Tech Corp; Manufacturer Part Number: 0805N120J101
footprint CAP-0805 (0805 (2012M) Capacitor)
pins: 1, 2

## 0805N120J251CT
designator C?  Capacitance: 12pF  (hidden comment: *)
Capacitor, Ceramic (MLCC), 12pF, ±5%, 250V, NP0, ±5%, SMD 0805; Manufacturer: Walsin Tech Corp; Manufacturer Part Number: 0805N120J251CT
footprint CAP-0805 (0805 (2012M) Capacitor)
pins: 1, 2

## 0805N120J500CT
designator C?  Capacitance: 12pF  (hidden comment: *)
Capacitor, Ceramic (MLCC), 12pF, ±5%, 50V, NP0, ±5%, SMD 0805; Manufacturer: Walsin Tech Corp; Manufacturer Part Number: 0805N120J500CT
footprint CAP-0805 (0805 (2012M) Capacitor)
pins: 1, 2

## 0805N121J201CT
designator C?  Capacitance: 120pF  (hidden comment: *)
Capacitor, Ceramic (MLCC), 120pF, ±5%, 200V, NP0, ±5%, SMD 0805; Manufacturer: Walsin Tech Corp; Manufacturer Part Number: 0805N121J201CT
footprint CAP-0805 (0805 (2012M) Capacitor)
pins: 1, 2

## 0805N121J500CT
designator C?  Capacitance: 120pF  (hidden comment: *)
Capacitor, Ceramic (MLCC), 120pF, ±5%, 50V, NP0, ±5%, SMD 0805; Manufacturer: Walsin Tech Corp; Manufacturer Part Number: 0805N121J500CT
footprint CAP-0805 (0805 (2012M) Capacitor)
pins: 1, 2

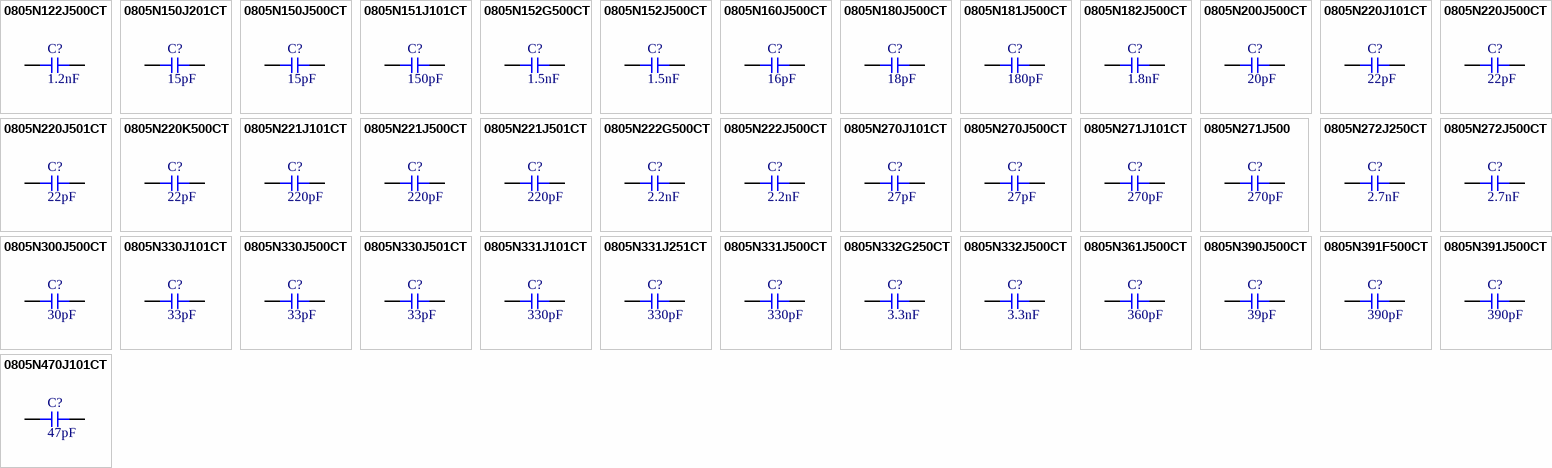
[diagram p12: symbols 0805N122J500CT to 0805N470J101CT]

## 0805N122J500CT
designator C?  Capacitance: 1.2nF  (hidden comment: *)
Capacitor, Ceramic (MLCC), 1.2nF, ±5%, 50V, NP0, ±5%, SMD 0805; Manufacturer: Walsin Tech Corp; Manufacturer Part Number: 0805N122J500CT
footprint CAP-0805 (0805 (2012M) Capacitor)
pins: 1, 2

## 0805N150J201CT
designator C?  Capacitance: 15pF  (hidden comment: *)
Capacitor, Ceramic (MLCC), 15pF, ±5%, 200V, NP0, ±5%, SMD 0805; Manufacturer: Walsin Tech Corp; Manufacturer Part Number: 0805N150J201CT
footprint CAP-0805 (0805 (2012M) Capacitor)
pins: 1, 2

## 0805N150J500CT
designator C?  Capacitance: 15pF  (hidden comment: *)
Capacitor, Ceramic (MLCC), 15pF, ±5%, 50V, NP0, ±5%, SMD 0805; Manufacturer: Walsin Tech Corp; Manufacturer Part Number: 0805N150J500CT
footprint CAP-0805 (0805 (2012M) Capacitor)
pins: 1, 2

## 0805N151J101CT
designator C?  Capacitance: 150pF  (hidden comment: *)
Capacitor, Ceramic (MLCC), 150pF, ±5%, 100V, NP0, ±5%, SMD 0805; Manufacturer: Walsin Tech Corp; Manufacturer Part Number: 0805N151J101CT
footprint CAP-0805 (0805 (2012M) Capacitor)
pins: 1, 2

## 0805N152G500CT
designator C?  Capacitance: 1.5nF  (hidden comment: *)
Capacitor, Ceramic (MLCC), 1.5nF, ±2%, 50V, NP0, ±2%, SMD 0805; Manufacturer: Walsin Tech Corp; Manufacturer Part Number: 0805N152G500CT
footprint CAP-0805 (0805 (2012M) Capacitor)
pins: 1, 2

## 0805N152J500CT
designator C?  Capacitance: 1.5nF  (hidden comment: *)
Capacitor, Ceramic (MLCC), 1.5nF, ±5%, 50V, NP0, ±5%, SMD 0805; Manufacturer: Walsin Tech Corp; Manufacturer Part Number: 0805N152J500CT
footprint CAP-0805 (0805 (2012M) Capacitor)
pins: 1, 2

## 0805N160J500CT
designator C?  Capacitance: 16pF  (hidden comment: *)
Capacitor, Ceramic (MLCC), 16pF, ±5%, 50V, NP0, ±5%, SMD 0805; Manufacturer: Walsin Tech Corp; Manufacturer Part Number: 0805N160J500CT
footprint CAP-0805 (0805 (2012M) Capacitor)
pins: 1, 2

## 0805N180J500CT
designator C?  Capacitance: 18pF  (hidden comment: *)
Capacitor, Ceramic (MLCC), 18pF, ±5%, 50V, NP0, ±5%, SMD 0805; Manufacturer: Walsin Tech Corp; Manufacturer Part Number: 0805N180J500CT
footprint CAP-0805 (0805 (2012M) Capacitor)
pins: 1, 2

## 0805N181J500CT
designator C?  Capacitance: 180pF  (hidden comment: *)
Capacitor, Ceramic (MLCC), 180pF, ±5%, 50V, NP0, ±5%, SMD 0805; Manufacturer: Walsin Tech Corp; Manufacturer Part Number: 0805N181J500CT
footprint CAP-0805 (0805 (2012M) Capacitor)
pins: 1, 2

## 0805N182J500CT
designator C?  Capacitance: 1.8nF  (hidden comment: *)
Capacitor, Ceramic (MLCC), 1.8nF, ±5%, 50V, NP0, ±5%, SMD 0805; Manufacturer: Walsin Tech Corp; Manufacturer Part Number: 0805N182J500CT
footprint CAP-0805 (0805 (2012M) Capacitor)
pins: 1, 2

## 0805N200J500CT
designator C?  Capacitance: 20pF  (hidden comment: *)
Capacitor, Ceramic (MLCC), 20pF, ±5%, 50V, NP0, ±5%, SMD 0805; Manufacturer: Walsin Tech Corp; Manufacturer Part Number: 0805N200J500CT
footprint CAP-0805 (0805 (2012M) Capacitor)
pins: 1, 2

## 0805N220J101CT
designator C?  Capacitance: 22pF  (hidden comment: *)
Capacitor, Ceramic (MLCC), 22pF, ±5%, 100V, NP0, ±5%, SMD 0805; Manufacturer: Walsin Tech Corp; Manufacturer Part Number: 0805N220J101CT
footprint CAP-0805 (0805 (2012M) Capacitor)
pins: 1, 2

## 0805N220J500CT
designator C?  Capacitance: 22pF  (hidden comment: *)
Capacitor, Ceramic (MLCC), 22pF, ±5%, 50V, NP0, ±5%, SMD 0805; Manufacturer: Walsin Tech Corp; Manufacturer Part Number: 0805N220J500CT
footprint CAP-0805 (0805 (2012M) Capacitor)
pins: 1, 2

## 0805N220J501CT
designator C?  Capacitance: 22pF  (hidden comment: *)
Capacitor, Ceramic (MLCC), 22pF, ±5%, 500V, NP0, ±5%, SMD 0805; Manufacturer: Walsin Tech Corp; Manufacturer Part Number: 0805N220J501CT
footprint CAP-0805 (0805 (2012M) Capacitor)
pins: 1, 2

## 0805N220K500CT
designator C?  Capacitance: 22pF  (hidden comment: *)
Capacitor, Ceramic (MLCC), 22pF, ±10%, 50V, NP0, ±10%, SMD 0805; Manufacturer: Walsin Tech Corp; Manufacturer Part Number: 0805N220K500CT
footprint CAP-0805 (0805 (2012M) Capacitor)
pins: 1, 2

## 0805N221J101CT
designator C?  Capacitance: 220pF  (hidden comment: *)
Capacitor, Ceramic (MLCC), 220pF, ±5%, 100V, NP0, ±5%, SMD 0805; Manufacturer: Walsin Tech Corp; Manufacturer Part Number: 0805N221J101CT
footprint CAP-0805 (0805 (2012M) Capacitor)
pins: 1, 2

## 0805N221J500CT
designator C?  Capacitance: 220pF  (hidden comment: *)
Capacitor, Ceramic (MLCC), 220pF, ±5%, 50V, NP0, ±5%, SMD 0805; Manufacturer: Walsin Tech Corp; Manufacturer Part Number: 0805N221J500CT
footprint CAP-0805 (0805 (2012M) Capacitor)
pins: 1, 2

## 0805N221J501CT
designator C?  Capacitance: 220pF  (hidden comment: *)
Capacitor, Ceramic (MLCC), 220pF, ±5%, 500V, NP0, ±5%, SMD 0805; Manufacturer: Walsin Tech Corp; Manufacturer Part Number: 0805N221J501CT
footprint CAP-0805 (0805 (2012M) Capacitor)
pins: 1, 2

## 0805N222G500CT
designator C?  Capacitance: 2.2nF  (hidden comment: *)
Capacitor, Ceramic (MLCC), 2.2nF, ±2%, 50V, NP0, ±2%, SMD 0805; Manufacturer: Walsin Tech Corp; Manufacturer Part Number: 0805N222G500CT
footprint CAP-0805 (0805 (2012M) Capacitor)
pins: 1, 2

## 0805N222J500CT
designator C?  Capacitance: 2.2nF  (hidden comment: *)
Capacitor, Ceramic (MLCC), 2.2nF, ±5%, 50V, NP0, ±5%, SMD 0805; Manufacturer: Walsin Tech Corp; Manufacturer Part Number: 0805N222J500CT
footprint CAP-0805 (0805 (2012M) Capacitor)
pins: 1, 2

## 0805N270J101CT
designator C?  Capacitance: 27pF  (hidden comment: *)
Capacitor, Ceramic (MLCC), 27pF, ±5%, 100V, NP0, ±5%, SMD 0805; Manufacturer: Walsin Tech Corp; Manufacturer Part Number: 0805N270J101CT
footprint CAP-0805 (0805 (2012M) Capacitor)
pins: 1, 2

## 0805N270J500CT
designator C?  Capacitance: 27pF  (hidden comment: *)
Capacitor, Ceramic (MLCC), 27pF, ±5%, 50V, NP0, ±5%, SMD 0805; Manufacturer: Walsin Tech Corp; Manufacturer Part Number: 0805N270J500CT
footprint CAP-0805 (0805 (2012M) Capacitor)
pins: 1, 2

## 0805N271J101CT
designator C?  Capacitance: 270pF  (hidden comment: *)
Capacitor, Ceramic (MLCC), 270pF, ±5%, 100V, NP0, ±5%, SMD 0805; Manufacturer: Walsin Tech Corp; Manufacturer Part Number: 0805N271J101CT
footprint CAP-0805 (0805 (2012M) Capacitor)
pins: 1, 2

## 0805N271J500
designator C?  Capacitance: 270pF  (hidden comment: *)
Capacitor, Ceramic (MLCC), 270pF, ±5%, 50V, NP0, ±5%, SMD 0805; Manufacturer: Walsin Tech Corp; Manufacturer Part Number: 0805N271J500
footprint CAP-0805 (0805 (2012M) Capacitor)
pins: 1, 2

## 0805N272J250CT
designator C?  Capacitance: 2.7nF  (hidden comment: *)
Capacitor, Ceramic (MLCC), 2.7nF, ±5%, 25V, NP0, ±5%, SMD 0805; Manufacturer: Walsin Tech Corp; Manufacturer Part Number: 0805N272J250CT
footprint CAP-0805 (0805 (2012M) Capacitor)
pins: 1, 2

## 0805N272J500CT
designator C?  Capacitance: 2.7nF  (hidden comment: *)
Capacitor, Ceramic (MLCC), 2.7nF, ±5%, 50V, NP0, ±5%, SMD 0805; Manufacturer: Walsin Tech Corp; Manufacturer Part Number: 0805N272J500CT
footprint CAP-0805 (0805 (2012M) Capacitor)
pins: 1, 2

## 0805N300J500CT
designator C?  Capacitance: 30pF  (hidden comment: *)
Capacitor, Ceramic (MLCC), 30pF, ±5%, 50V, NP0, ±5%, SMD 0805; Manufacturer: Walsin Tech Corp; Manufacturer Part Number: 0805N300J500CT
footprint CAP-0805 (0805 (2012M) Capacitor)
pins: 1, 2

## 0805N330J101CT
designator C?  Capacitance: 33pF  (hidden comment: *)
Capacitor, Ceramic (MLCC), 33pF, ±5%, 100V, NP0, ±5%, SMD 0805; Manufacturer: Walsin Tech Corp; Manufacturer Part Number: 0805N330J101CT
footprint CAP-0805 (0805 (2012M) Capacitor)
pins: 1, 2

## 0805N330J500CT
designator C?  Capacitance: 33pF  (hidden comment: *)
Capacitor, Ceramic (MLCC), 33pF, ±5%, 50V, NP0, ±5%, SMD 0805; Manufacturer: Walsin Tech Corp; Manufacturer Part Number: 0805N330J500CT
footprint CAP-0805 (0805 (2012M) Capacitor)
pins: 1, 2

## 0805N330J501CT
designator C?  Capacitance: 33pF  (hidden comment: *)
Capacitor, Ceramic (MLCC), 33pF, ±5%, 500V, NP0, ±5%, SMD 0805; Manufacturer: Walsin Tech Corp; Manufacturer Part Number: 0805N330J501CT
footprint CAP-0805 (0805 (2012M) Capacitor)
pins: 1, 2

## 0805N331J101CT
designator C?  Capacitance: 330pF  (hidden comment: *)
Capacitor, Ceramic (MLCC), 330pF, ±5%, 100V, NP0, ±5%, SMD 0805; Manufacturer: Walsin Tech Corp; Manufacturer Part Number: 0805N331J101CT
footprint CAP-0805 (0805 (2012M) Capacitor)
pins: 1, 2

## 0805N331J251CT
designator C?  Capacitance: 330pF  (hidden comment: *)
Capacitor, Ceramic (MLCC), 330pF, ±5%, 250V, NP0, ±5%, SMD 0805; Manufacturer: Walsin Tech Corp; Manufacturer Part Number: 0805N331J251CT
footprint CAP-0805 (0805 (2012M) Capacitor)
pins: 1, 2

## 0805N331J500CT
designator C?  Capacitance: 330pF  (hidden comment: *)
Capacitor, Ceramic (MLCC), 330pF, ±5%, 50V, NP0, ±5%, SMD 0805; Manufacturer: Walsin Tech Corp; Manufacturer Part Number: 0805N331J500CT
footprint CAP-0805 (0805 (2012M) Capacitor)
pins: 1, 2

## 0805N332G250CT
designator C?  Capacitance: 3.3nF  (hidden comment: *)
Capacitor, Ceramic (MLCC), 3.3nF, ±2%, 25V, NP0, ±2%, SMD 0805; Manufacturer: Walsin Tech Corp; Manufacturer Part Number: 0805N332G250CT
footprint CAP-0805 (0805 (2012M) Capacitor)
pins: 1, 2

## 0805N332J500CT
designator C?  Capacitance: 3.3nF  (hidden comment: *)
Capacitor, Ceramic (MLCC), 3.3nF, ±5%, 50V, NP0, ±5%, SMD 0805; Manufacturer: Walsin Tech Corp; Manufacturer Part Number: 0805N332J500CT
footprint CAP-0805 (0805 (2012M) Capacitor)
pins: 1, 2

## 0805N361J500CT
designator C?  Capacitance: 360pF  (hidden comment: *)
Capacitor, Ceramic (MLCC), 360pF, ±5%, 50V, NP0, ±5%, SMD 0805; Manufacturer: Walsin Tech Corp; Manufacturer Part Number: 0805N361J500CT
footprint CAP-0805 (0805 (2012M) Capacitor)
pins: 1, 2

## 0805N390J500CT
designator C?  Capacitance: 39pF  (hidden comment: *)
Capacitor, Ceramic (MLCC), 39pF, ±5%, 50V, NP0, ±5%, SMD 0805; Manufacturer: Walsin Tech Corp; Manufacturer Part Number: 0805N390J500CT
footprint CAP-0805 (0805 (2012M) Capacitor)
pins: 1, 2

## 0805N391F500CT
designator C?  Capacitance: 390pF  (hidden comment: *)
Capacitor, Ceramic (MLCC), 390pF, ±1%, 50V, NP0, ±1%, SMD 0805; Manufacturer: Walsin Tech Corp; Manufacturer Part Number: 0805N391F500CT
footprint CAP-0805 (0805 (2012M) Capacitor)
pins: 1, 2

## 0805N391J500CT
designator C?  Capacitance: 390pF  (hidden comment: *)
Capacitor, Ceramic (MLCC), 390pF, ±5%, 50V, NP0, ±5%, SMD 0805; Manufacturer: Walsin Tech Corp; Manufacturer Part Number: 0805N391J500CT
footprint CAP-0805 (0805 (2012M) Capacitor)
pins: 1, 2

## 0805N470J101CT
designator C?  Capacitance: 47pF  (hidden comment: *)
Capacitor, Ceramic (MLCC), 47pF, ±5%, 100V, NP0, ±5%, SMD 0805; Manufacturer: Walsin Tech Corp; Manufacturer Part Number: 0805N470J101CT
footprint CAP-0805 (0805 (2012M) Capacitor)
pins: 1, 2

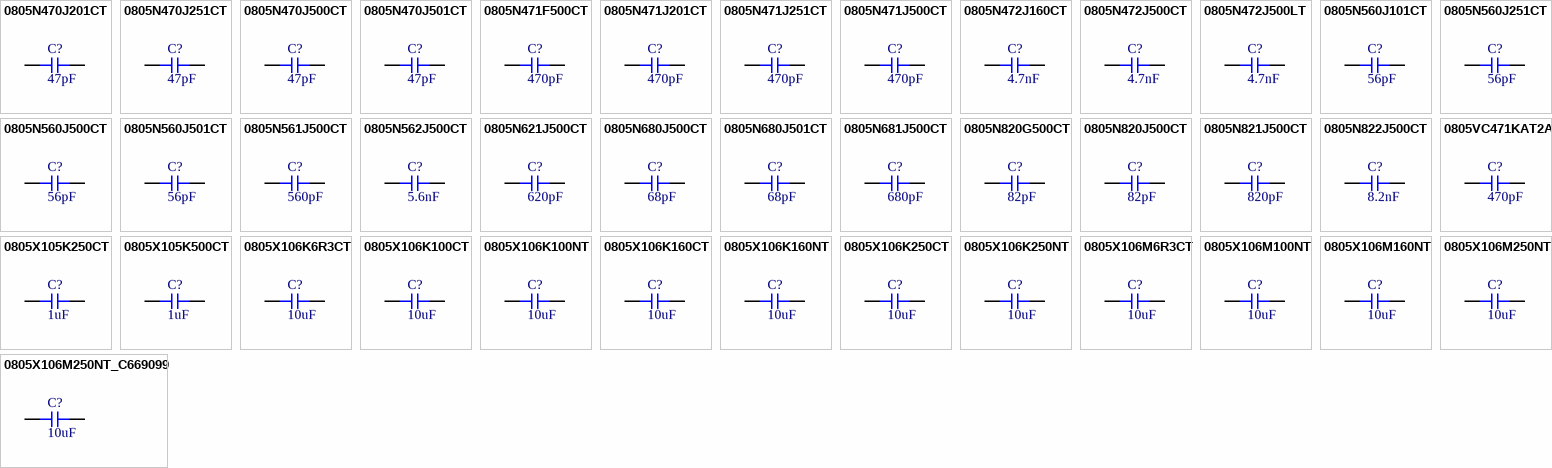
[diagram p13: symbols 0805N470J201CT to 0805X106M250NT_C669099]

## 0805N470J201CT
designator C?  Capacitance: 47pF  (hidden comment: *)
Capacitor, Ceramic (MLCC), 47pF, ±5%, 200V, NP0, ±5%, SMD 0805; Manufacturer: Walsin Tech Corp; Manufacturer Part Number: 0805N470J201CT
footprint CAP-0805 (0805 (2012M) Capacitor)
pins: 1, 2

## 0805N470J251CT
designator C?  Capacitance: 47pF  (hidden comment: *)
Capacitor, Ceramic (MLCC), 47pF, ±5%, 250V, NP0, ±5%, SMD 0805; Manufacturer: Walsin Tech Corp; Manufacturer Part Number: 0805N470J251CT
footprint CAP-0805 (0805 (2012M) Capacitor)
pins: 1, 2

## 0805N470J500CT
designator C?  Capacitance: 47pF  (hidden comment: *)
Capacitor, Ceramic (MLCC), 47pF, ±5%, 50V, NP0, ±5%, SMD 0805; Manufacturer: Walsin Tech Corp; Manufacturer Part Number: 0805N470J500CT
footprint CAP-0805 (0805 (2012M) Capacitor)
pins: 1, 2

## 0805N470J501CT
designator C?  Capacitance: 47pF  (hidden comment: *)
Capacitor, Ceramic (MLCC), 47pF, ±5%, 500V, NP0, ±5%, SMD 0805; Manufacturer: Walsin Tech Corp; Manufacturer Part Number: 0805N470J501CT
footprint CAP-0805 (0805 (2012M) Capacitor)
pins: 1, 2

## 0805N471F500CT
designator C?  Capacitance: 470pF  (hidden comment: *)
Capacitor, Ceramic (MLCC), 470pF, ±1%, 50V, NP0, ±1%, SMD 0805; Manufacturer: Walsin Tech Corp; Manufacturer Part Number: 0805N471F500CT
footprint CAP-0805 (0805 (2012M) Capacitor)
pins: 1, 2

## 0805N471J201CT
designator C?  Capacitance: 470pF  (hidden comment: *)
Capacitor, Ceramic (MLCC), 470pF, ±5%, 200V, NP0, ±5%, SMD 0805; Manufacturer: Walsin Tech Corp; Manufacturer Part Number: 0805N471J201CT
footprint CAP-0805 (0805 (2012M) Capacitor)
pins: 1, 2

## 0805N471J251CT
designator C?  Capacitance: 470pF  (hidden comment: *)
Capacitor, Ceramic (MLCC), 470pF, ±5%, 250V, NP0, ±5%, SMD 0805; Manufacturer: Walsin Tech Corp; Manufacturer Part Number: 0805N471J251CT
footprint CAP-0805 (0805 (2012M) Capacitor)
pins: 1, 2

## 0805N471J500CT
designator C?  Capacitance: 470pF  (hidden comment: *)
Capacitor, Ceramic (MLCC), 470pF, ±5%, 50V, NP0, ±5%, SMD 0805; Manufacturer: Walsin Tech Corp; Manufacturer Part Number: 0805N471J500CT
footprint CAP-0805 (0805 (2012M) Capacitor)
pins: 1, 2

## 0805N472J160CT
designator C?  Capacitance: 4.7nF  (hidden comment: *)
Capacitor, Ceramic (MLCC), 4.7nF, ±5%, 16V, NP0, ±5%, SMD 0805; Manufacturer: Walsin Tech Corp; Manufacturer Part Number: 0805N472J160CT
footprint CAP-0805 (0805 (2012M) Capacitor)
pins: 1, 2

## 0805N472J500CT
designator C?  Capacitance: 4.7nF  (hidden comment: *)
Capacitor, Ceramic (MLCC), 4.7nF, ±5%, 50V, NP0, ±5%, SMD 0805; Manufacturer: Walsin Tech Corp; Manufacturer Part Number: 0805N472J500CT
footprint CAP-0805 (0805 (2012M) Capacitor)
pins: 1, 2

## 0805N472J500LT
designator C?  Capacitance: 4.7nF  (hidden comment: *)
Capacitor, Ceramic (MLCC), 4.7nF, ±5%, 50V, NP0, ±5%, SMD 0805; Manufacturer: Walsin Tech Corp; Manufacturer Part Number: 0805N472J500LT
footprint CAP-0805 (0805 (2012M) Capacitor)
pins: 1, 2

## 0805N560J101CT
designator C?  Capacitance: 56pF  (hidden comment: *)
Capacitor, Ceramic (MLCC), 56pF, ±5%, 100V, NP0, ±5%, SMD 0805; Manufacturer: Walsin Tech Corp; Manufacturer Part Number: 0805N560J101CT
footprint CAP-0805 (0805 (2012M) Capacitor)
pins: 1, 2

## 0805N560J251CT
designator C?  Capacitance: 56pF  (hidden comment: *)
Capacitor, Ceramic (MLCC), 56pF, ±5%, 250V, NP0, ±5%, SMD 0805; Manufacturer: Walsin Tech Corp; Manufacturer Part Number: 0805N560J251CT
footprint CAP-0805 (0805 (2012M) Capacitor)
pins: 1, 2

## 0805N560J500CT
designator C?  Capacitance: 56pF  (hidden comment: *)
Capacitor, Ceramic (MLCC), 56pF, ±5%, 50V, NP0, ±5%, SMD 0805; Manufacturer: Walsin Tech Corp; Manufacturer Part Number: 0805N560J500CT
footprint CAP-0805 (0805 (2012M) Capacitor)
pins: 1, 2

## 0805N560J501CT
designator C?  Capacitance: 56pF  (hidden comment: *)
Capacitor, Ceramic (MLCC), 56pF, ±5%, 500V, NP0, ±5%, SMD 0805; Manufacturer: Walsin Tech Corp; Manufacturer Part Number: 0805N560J501CT
footprint CAP-0805 (0805 (2012M) Capacitor)
pins: 1, 2

## 0805N561J500CT
designator C?  Capacitance: 560pF  (hidden comment: *)
Capacitor, Ceramic (MLCC), 560pF, ±5%, 50V, NP0, ±5%, SMD 0805; Manufacturer: Walsin Tech Corp; Manufacturer Part Number: 0805N561J500CT
footprint CAP-0805 (0805 (2012M) Capacitor)
pins: 1, 2

## 0805N562J500CT
designator C?  Capacitance: 5.6nF  (hidden comment: *)
Capacitor, Ceramic (MLCC), 5.6nF, ±5%, 50V, NP0, ±5%, SMD 0805; Manufacturer: Walsin Tech Corp; Manufacturer Part Number: 0805N562J500CT
footprint CAP-0805 (0805 (2012M) Capacitor)
pins: 1, 2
